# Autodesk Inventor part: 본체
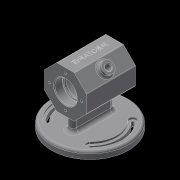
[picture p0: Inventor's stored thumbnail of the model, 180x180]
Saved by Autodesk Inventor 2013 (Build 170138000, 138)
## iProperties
Created: 2017-06
Part Number: 본체
Material: 일반
Document SubType Name: Modeling
Designer: Administrator
Density: 1 g/cm^3
Author: Administrator
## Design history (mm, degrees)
sketch "스케치1"
  geometry: L1 (12.426, 30)-(30, 12.426); L2 (30, 12.426)-(30, -12.426); L3 (30, -12.426)-(12.426, -30); L4 (12.426, -30)-(-12.426, -30); L5 (-12.426, -30)-(-30, -12.426); L6 (-30, -12.426)-(-30, 12.426); L7 (-30, 12.426)-(-12.426, 30); L8 (-12.426, 30)-(12.426, 30); C1 r 30 at (0, 0); 2 further points
  constraints: 16 end point, 2 coincident, 1 centre point, 1 horizontal, 1 tangent, 17 other
  dimensions: "d2" = 60 diameter of C1
extrude "돌출1" new body sketch "스케치1" distance "d0" = 70; taper "d1" = 0 deg
sketch "스케치2" dims "d4" = 46
  geometry: 3 further points
  constraints: 2 vertical alignment, 1 coincident, 2 other
hole "구멍1" sketch "스케치2" at (0, 23) diameter "d6" = 3.242; stored, may be unused: countersink angle "d10" = 90 deg, drill point angle "d12" = 118 deg; dims "d7" = 8, "d8" = 4, "d9" = 2, "d11" = 10
sketch "스케치3"
  geometry: L1 (0, 0)-(70, 0); L2 (0, 0)-(0, 16); L3 (0, 16)-(12, 16); L4 (12, 16)-(12, 14); L5 (12, 14)-(15, 14); L6 (15, 14)-(15, 25); L7 (15, 25)-(55, 25); L8 (55, 25)-(55, 14); L9 (55, 14)-(58, 14); L10 (58, 14)-(58, 16); L11 (58, 16)-(70, 16); L12 (70, 16)-(70, 0); L13 (70, -12.426)-(70, 12.426) reference; 1 further point
  constraints: 24 end point, 6 parallel, 3 perpendicular, 2 collinear, 2 horizontal, 1 coincident, 1 midpoint
  dimensions: "d13" = 32 diameter of L3 L1; "d15" = 28 diameter of L5 L1; "d16" = 50 diameter of L7 L1; "d17" = 32 diameter of L11 L1; "d18" = 28 diameter of L9 L1; "d19" = 12 distance of L2.end L3.end; "d20" = 40 distance of L6.end L7.end; "d21" = 12 distance of L10.end L11.end; "d22" = 3 distance of L4.end L5.end
revolve "회전1" sketch "스케치3" stored, may be unused: angle "d23" = 90 deg
node "작업 평면1"
node "작업 평면2"
sketch "스케치4"
  geometry: L1 (12.426, 0)-(-12.426, 0) reference; L2 (-12.426, 70)-(12.426, 70) reference; L3 (0, 0)-(0, 70); C1 r 55 at (0, 35)
  constraints: 2 end point, 2 midpoint, 1 centre point
  dimensions: "d28" = 110 diameter of C1
extrude "돌출2" join sketch "스케치4" distance "d30" = 10; taper "d31" = 0 deg
sketch "스케치5"
  geometry: L1 (0, 0)-(-33.941, -33.941); L2 (0, 0)-(-33.941, 33.941); L3 (0, 0)-(-55, 0); A1 r 48 centre (0, 0) between (-33.941, 33.941) and (-33.941, -33.941); A2 r 5 centre (-30.406, -30.406) between (-33.941, -33.941) and (-26.87, -26.87); A3 r 5 centre (-30.406, 30.406) between (-26.87, 26.87) and (-33.941, 33.941); A4 r 38 centre (0, 0) between (-26.87, 26.87) and (-26.87, -26.87); 1 further point
  constraints: 9 point on circle, 6 end point, 4 centre point, 3 tangent, 2 coincident, 2 point on line, 1 horizontal, 1 horizontal alignment, 1 other
  dimensions: "d33" = 5 radius of A2; "d35" = 90 deg angle of L2 L1; "d37" = 45 deg angle of L3 L1; "d39" = 48 radius of A1
extrude "돌출3" cut sketch "스케치5" distance "d40" = 3; taper "d41" = 0 deg
sketch "스케치6"
  geometry: A1 r 48 centre (0, 0) between (-33.941, 33.941) and (-33.941, -33.941) reference; A2 r 5 centre (-30.406, -30.406) between (-33.941, -33.941) and (-26.87, -26.87) reference; A3 r 38 centre (0, 0) between (-26.87, 26.87) and (-26.87, -26.87) reference; A4 r 5 centre (-30.406, 30.406) between (-26.87, 26.87) and (-33.941, 33.941) reference; A5 r 45 centre (0, 0) between (-31.82, 31.82) and (-31.82, -31.82); A6 r 2 centre (-30.406, 30.406) between (-28.991, 28.991) and (-31.82, 31.82); A7 r 41 centre (0, 0) between (-28.991, 28.991) and (-28.991, -28.991); A8 r 2 centre (-30.406, -30.406) between (-31.82, -31.82) and (-28.991, -28.991); 1 further point
  constraints: 8 point on circle, 4 centre point, 3 other
  dimensions: "d42" = 2 radius of A6
extrude "돌출4" cut sketch "스케치6" stored distance "d44" = 3; taper "d45" = 0 deg
sketch "스케치7"
  geometry: L1 (-5, -24)-(-5, 24); L2 (5, 24)-(5, -24); A1 r 38 centre (0, 0) between (26.87, -26.87) and (26.87, 26.87) reference; A2 r 48 centre (0, 0) between (-33.941, 33.941) and (-33.941, -33.941) reference; A3 r 5 centre (0, 24) between (5, 24) and (-5, 24); A4 r 5 centre (0, -24) between (-5, -24) and (5, -24); 3 further points
  constraints: 5 point on circle, 4 end point, 3 tangent, 2 centre point, 1 horizontal alignment, 1 midpoint, 1 parallel, 1 vertical, 1 vertical alignment
  dimensions: "d46" = 5 radius of A4; "d48" = 5 radius of A3; "d49" = 48 distance of L1.start L1.end
extrude "돌출5" join sketch "스케치7" stored distance "d50" = 3; taper "d51" = 0 deg
sketch "스케치8"
  geometry: L1 (-12.426, 30)-(-30, 12.426) reference; L2 (-30, 12.426)-(-30, -12.426) reference; L3 (-30, -12.426)-(-12.426, -30) reference; L4 (-12.426, -30)-(12.426, -30) reference; L5 (12.426, -30)-(30, -12.426) reference; L6 (30, -12.426)-(30, 12.426) reference; L7 (30, 12.426)-(12.426, 30) reference; L8 (12.426, 30)-(-12.426, 30) reference; L9 (0, 0)-(0, 23); L10 (0, 0)-(26.163, 26.163); C1 r 1.621 at (23, 0) reference; C2 r 1.621 at (0, -23) reference; C3 r 1.621 at (-23, 0) reference; C4 r 16 at (0, 0) reference; C5 r 1.621 at (0, 23) reference
  constraints: 4 end point, 1 perpendicular
  dimensions: "d52" = 45 deg angle of L10 L9; "d53" = 7 distance from line of L10.end L7
node "작업 평면3"
sketch "스케치9"
  geometry: L1 (0, 12.426)-(70, 12.426) reference; C1 r 8 at (35, 0); 3 further points
  constraints: 1 centre point, 1 horizontal alignment, 1 midpoint, 1 vertical alignment
  dimensions: "d54" = 16 diameter of C1
extrude "돌출6" join sketch "스케치9" stored distance "d56" = 3; taper "d57" = 0 deg
hole "구멍2" diameter "d60" = 8; stored, may be unused: countersink angle "d64" = 90 deg, drill point angle "d66" = 0 deg; dims "d61" = 8, "d62" = 4, "d63" = 2, "d65" = 40, "d69" = 10, "d70" = 10
node "작업 평면4"
sketch "스케치10"
  geometry: L1 (0, 0)-(-17.574, 0) reference; L2 (-17.574, 0)-(-17.574, 70) reference; 2 further points
  constraints: 1 other
  dimensions: "d68" = 35 distance from line of point (12.426, 35) L1; "d71" = 30 distance from line of point (12.426, 35) L2
feature "엠보싱1" sketch "스케치10" dims "d13" = 32, "d15" = 28, "d16" = 50, "d17" = 32, "d18" = 28, "d19" = 12, "d20" = 40, "d21" = 12, "d22" = 3, "d72" = 0.5, "d73" = 0
chamfer "모따기1" distance "d74" = 1; stored, may be unused: second distance "d75" = 2, angle "d76" = 45 deg
fillet "모깎기1" dims "d77" = 3, "d78" = 1, "d81" = 5
fillet "모깎기2" dims "d79" = 0.3, "d80" = 3
node "솔리드1"
pattern_circular "원형 패턴1" dims angle "d25" = 360 deg
mirror "대칭1"
mirror "대칭2"
other parameters: "d27" = -62, "d67" = 48.75
